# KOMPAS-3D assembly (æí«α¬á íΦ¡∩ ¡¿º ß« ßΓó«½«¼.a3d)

Referenced files in D:\МОДЕЛЬ ТАНКА Т90\ДЕТАЛИ\БАШНЯ\башня сварная\: основание башни.m3d, Сборка орудие с маской.a3d, серво.m3d, рычаг серво.m3d, тяга.m3d
Referenced files in D:\МОДЕЛЬ ТАНКА Т90\ДЕТАЛИ\ОБЩИЕ ДЕТАЛИ\: гироскоп датчик.m3d
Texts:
  Сборка бшня низ со стволом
